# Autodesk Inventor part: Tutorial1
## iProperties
Shininess: 77.0
Length Units: 11269
Angle Units: 11279
Time Units: 11290
Mass Units: 11283
Length Display Precision: 3
Angle Display Precision: 2
Created: 2001-12
Part Number: Tutorial1
Document SubType Name: Modeling
Designer: Renu Muthoo
Density: 1 g/cm^3
Density: 0.0
Volumn: 0.0
Area: 0.0
PropertySet Name: Model Information
Control State: 0
Master: False
Checked Out: False
Author: Renu Muthoo
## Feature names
1. Extrusion1
2. Extrusion2
3. Fillet1
4. Hole1
5. Extrusion3
